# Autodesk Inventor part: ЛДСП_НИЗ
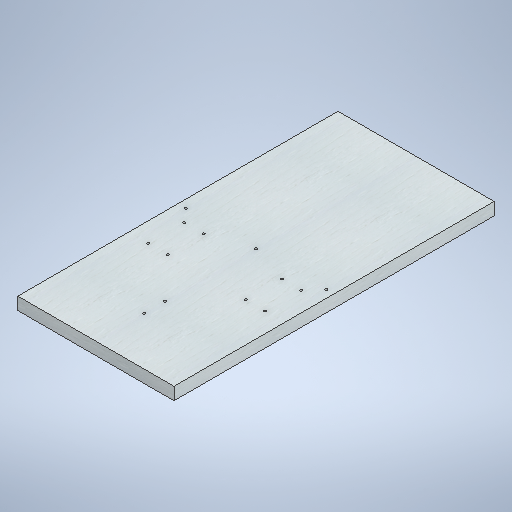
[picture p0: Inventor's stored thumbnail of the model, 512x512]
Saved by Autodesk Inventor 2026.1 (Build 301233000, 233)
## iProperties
Created: 2025-12
Part Number: ЛДСП_НИЗ
Material: Типовые
Document SubType Name: Modeling
Designer: Yury Melnikov
Density: 1 g/cm^3
Appearance: Дерево — окрашенное — белое
Author: Yury Melnikov
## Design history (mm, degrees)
sketch "Эскиз1"
  geometry: L1 (0, 410)-(-200, 410); L2 (-200, 410)-(-200, 0); L3 (-200, 0)-(0, 0); L4 (0, 0)-(0, 410); L5 (0, 205)-(-200, 205); C1 r 1.5 at (-10, 205); C2 r 1.5 at (-100, 205); C3 r 1.5 at (-190, 205); 1 further point
  constraints: 10 end point, 3 centre point, 2 horizontal, 2 midpoint, 2 parallel, 1 coincident, 1 perpendicular, 1 point on line, 4 other
  dimensions: "d0" = 200 distance of L3.end L2.end; "d1" = 410 distance of L2.end L1.end; "d4" = 90 distance of C1.centre C2.centre (derived); "d9" = 3 diameter of C1; "d10" = 10 distance from line of L4 C1.centre; "d11" = 10 distance from line of C3.centre L2
extrude "Выдавливание1" new body sketch "Эскиз1" distance "d12" = 16; taper "d13" = 0 deg
sketch "Эскиз2"
  geometry: L1 (0, -197)-(200, -197); L2 (200, -197)-(200, -213); L3 (200, -213)-(0, -213); L4 (0, -213)-(0, -197); L5 (0, 0)-(0, -410) reference; L6 (200, -410)-(200, 0) reference; L7 (25, -222)-(50, -222); L8 (50, -222)-(50, -268); L9 (50, -268)-(25, -268); L10 (25, -268)-(25, -222); L11 (100, -213)-(100, -235.73); L12 (175, -222)-(150, -222); L13 (175, -268)-(175, -222); L14 (150, -268)-(175, -268); L15 (150, -222)-(150, -268); C1 r 1.5 at (25, -222); C2 r 1.5 at (50, -222); C3 r 1.5 at (25, -268); C4 r 1.5 at (50, -268); C5 r 1.5 at (175, -222); C6 r 1.5 at (150, -222); C7 r 1.5 at (175, -268); C8 r 1.5 at (150, -268); 8 further points
  constraints: 26 end point, 11 symmetric about line, 8 centre point, 8 coincident, 4 parallel, 3 horizontal, 3 midpoint, 2 collinear, 2 perpendicular, 2 vertical, 1 horizontal alignment, 13 other
  dimensions: "d14" = 16 distance of L1.end L2.end; "d15" = 25 distance of L7.start L7.end; "d16" = 46 distance of L7.end L8.end; "d17" = 25 distance between parallel lines of L5 L10; "d18" = 9 distance between parallel lines of L7 L3; "d19" = 3 diameter of C1; "d22" = 25 distance of L7.start point (50, -222); "d25" = 46 distance of L7.start point (25, -268)
extrude "Выдавливание2" cut sketch "Эскиз2" distance "d28" = 15; taper "d29" = 0 deg
sketch "Эскиз3"
  geometry: L1 (0, -197)-(200, -197); L2 (200, -197)-(200, -213); L3 (200, -213)-(0, -213); L4 (0, -213)-(0, -197); L5 (200, -410)-(200, 0) reference; L6 (0, 0)-(0, -410) reference; L7 (0, -410)-(200, -410) reference; C1 r 1.5 at (100, -321.431); C2 r 1.5 at (100, -348); 3 further points
  constraints: 8 end point, 3 midpoint, 2 centre point, 2 collinear, 2 parallel, 2 vertical alignment, 1 coincident, 1 equal radius, 1 horizontal, 1 perpendicular
  dimensions: "d30" = 16 distance of L1.end L2.end; "d31" = 135 distance from line of C2.centre L3; "d32" = 26.569 distance of C2.centre C1.centre; "d33" = 3 diameter of C1
extrude "Выдавливание3" cut sketch "Эскиз3" distance "d34" = 16; taper "d35" = 0 deg
node "Твердое тело1"
node "Эскиз — прямоугольный массив1" dims "d4" = 90 (derived), "d7" = 10
node "Эскиз — прямоугольный массив2" dims "d22" = 25, "d25" = 46
